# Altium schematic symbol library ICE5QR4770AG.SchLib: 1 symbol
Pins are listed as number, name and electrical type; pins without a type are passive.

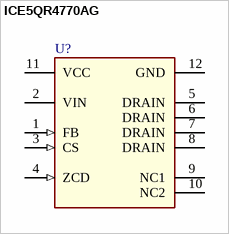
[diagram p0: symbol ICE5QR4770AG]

## ICE5QR4770AG
designator U?  (value not drawn)
Manufacturer: Infineon Technologies
footprint SOIC127P600X175-16_12N-1-V
footprint SOIC127P600X175-16_12N-1
pins: 1 FB (in), 2 VIN (power), 3 CS (in), 4 ZCD (in), 5 DRAIN (power), 6 DRAIN (power), 7 DRAIN (power), 8 DRAIN (power), 9 NC1, 10 NC2, 11 VCC (power), 12 GND (power)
